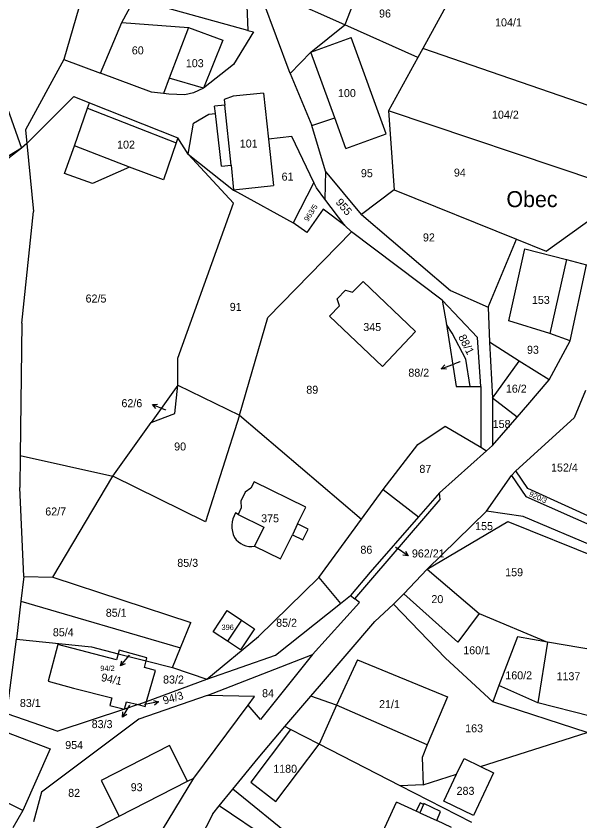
# Model space of a CAD drawing. Extents: x -593358 to -590116, y -1072518 to -1068420.
# Drawn here: x -591720.1 to -591600.3, y -1070728.7 to -1070557.8 of the extents above; entities that cross this region are included whole.
import ezdxf

# ---------------------------------------------------------------- set-up
doc = ezdxf.new("R2010")
doc.units = 0
for name, color, linetype in [('Názvosloví', 7, 'Continuous'), ('Parcela KN', 7, 'Continuous'), ('Parcelní číslo', 7, 'Continuous'), ('Parcelní číslo_stavební', 7, 'Continuous'), ('stavby - vnitřní kresba', 7, 'Continuous'), ('Vrstva 16', 7, 'Continuous')]:
    doc.layers.add(name, color=color, linetype=linetype)

msp = doc.modelspace()

# ---------------------------------------------------------------- linework, layer by layer
at = {"layer": 'Parcela KN'}
for p, q in [((-591700.37, -1070533.71), (-591709.96, -1070566.95)), ((-591671.59, -1070544.97), (-591670.83, -1070560.85)), ((-591647.2, -1070551.82), (-591650.26, -1070559.63)), ((-591697.64, -1070559.15), (-591694.95, -1070554.09)), ((-591670.83, -1070560.85), (-591694.95, -1070554.09)), ((-591661.85, -1070569.94), (-591667.67, -1070554.3)), ((-591628.45, -1070555.12), (-591633.68, -1070564.64)), ((-591702.13, -1070569.87), (-591697.64, -1070559.15)), ((-591697.64, -1070559.15), (-591683.44, -1070560.21)), ((-591683.44, -1070560.21), (-591687.54, -1070570.93)), ((-591683.44, -1070560.21), (-591676.15, -1070562.86)), ((-591657.46, -1070565.43), (-591650.26, -1070559.63)), ((-591634.74, -1070566.56), (-591650.26, -1070559.63)), ((-591676.15, -1070562.86), (-591680.28, -1070573.06)), ((-591657.46, -1070565.43), (-591648.91, -1070562.34)), ((-591641.5, -1070582.79), (-591648.91, -1070562.34)), ((-591725.94, -1070566.13), (-591718.97, -1070585.79)), ((-591657.46, -1070565.43), (-591661.85, -1070569.94)), ((-591633.68, -1070564.64), (-591634.74, -1070566.56)), ((-591591.64, -1070579.17), (-591633.68, -1070564.64)), ((-591709.96, -1070566.95), (-591718.13, -1070581.9)), ((-591709.96, -1070566.95), (-591702.13, -1070569.87)), ((-591634.74, -1070566.56), (-591641, -1070577.86)), ((-591691.32, -1070573.91), (-591702.13, -1070569.87)), ((-591687.54, -1070570.93), (-591688.81, -1070574.23)), ((-591680.28, -1070573.06), (-591687.54, -1070570.93)), ((-591661.85, -1070569.94), (-591657.25, -1070580.97)), ((-591707.85, -1070574.84), (-591717.83, -1070584.83)), ((-591707.85, -1070574.84), (-591704.51, -1070576.17)), ((-591688.81, -1070574.23), (-591691.32, -1070573.91)), ((-591673.96, -1070574.79), (-591675.88, -1070575.45)), ((-591667.5, -1070574.16), (-591673.96, -1070574.79)), ((-591667.5, -1070574.16), (-591666.46, -1070583.92)), ((-591704.9, -1070577.3), (-591704.51, -1070576.17)), ((-591704.51, -1070576.17), (-591685.71, -1070583.63)), ((-591675.88, -1070575.45), (-591675.78, -1070576.69)), ((-591707.71, -1070585.32), (-591704.9, -1070577.3)), ((-591675.78, -1070576.69), (-591677.94, -1070576.91)), ((-591677.76, -1070578.44), (-591677.94, -1070576.91)), ((-591595.29, -1070593.27), (-591641, -1070577.86)), ((-591641, -1070577.86), (-591639.75, -1070594.65)), ((-591682.43, -1070580.49), (-591679.13, -1070578.6)), ((-591679.13, -1070578.6), (-591677.76, -1070578.44)), ((-591676.46, -1070589.62), (-591677.76, -1070578.44)), ((-591657.25, -1070580.97), (-591652.39, -1070579.36)), ((-591650.02, -1070585.88), (-591652.39, -1070579.36)), ((-591683.56, -1070587.06), (-591682.43, -1070580.49)), ((-591654.33, -1070590.7), (-591657.25, -1070580.97)), ((-591718.13, -1070581.9), (-591717.83, -1070584.83)), ((-591661.52, -1070583.36), (-591666.46, -1070583.92)), ((-591656.8, -1070593.14), (-591661.52, -1070583.36)), ((-591650.02, -1070585.88), (-591641.5, -1070582.79)), ((-591717.83, -1070584.83), (-591718.97, -1070585.79)), ((-591717.83, -1070584.83), (-591716.37, -1070599.26)), ((-591686.08, -1070584.7), (-591688.76, -1070592.54)), ((-591685.71, -1070583.63), (-591686.08, -1070584.7)), ((-591683.56, -1070587.06), (-591685.71, -1070583.63)), ((-591666.46, -1070583.92), (-591665.41, -1070593.77)), ((-591718.97, -1070585.79), (-591725.69, -1070589.9)), ((-591718.97, -1070585.79), (-591723.12, -1070589.04)), ((-591709.78, -1070591.22), (-591707.71, -1070585.32)), ((-591683.56, -1070587.06), (-591673.9, -1070594.72)), ((-591673.91, -1070597.5), (-591683.56, -1070587.06)), ((-591695.98, -1070589.85), (-591703.88, -1070593.34)), ((-591688.76, -1070592.54), (-591695.98, -1070589.85)), ((-591676.46, -1070589.62), (-591674.43, -1070589.41)), ((-591674.43, -1070589.41), (-591673.89, -1070594.66)), ((-591703.88, -1070593.34), (-591709.78, -1070591.22)), ((-591654.33, -1070590.7), (-591654.47, -1070596.64)), ((-591646.73, -1070599.87), (-591654.33, -1070590.7)), ((-591656.8, -1070593.14), (-591661.24, -1070601.64)), ((-591656.25, -1070594.26), (-591656.8, -1070593.14)), ((-591673.9, -1070594.72), (-591673.08, -1070595.17)), ((-591673.89, -1070594.66), (-591665.41, -1070593.77)), ((-591673.08, -1070595.17), (-591661.24, -1070601.64)), ((-591654.47, -1070596.64), (-591656.25, -1070594.26)), ((-591639.75, -1070594.65), (-591646.73, -1070599.87)), ((-591639.75, -1070594.65), (-591613.79, -1070605.13)), ((-591650.26, -1070602.23), (-591654.47, -1070596.64)), ((-591685.73, -1070630.44), (-591673.91, -1070597.5)), ((-591654.82, -1070598.79), (-591658.3, -1070603.72)), ((-591650.26, -1070602.23), (-591654.82, -1070598.79)), ((-591718.9, -1070622.97), (-591716.37, -1070599.26)), ((-591646.73, -1070599.87), (-591627.76, -1070616.04)), ((-591607.46, -1070607.68), (-591596.91, -1070600.14)), ((-591658.3, -1070603.72), (-591661.24, -1070601.64)), ((-591666.62, -1070621.8), (-591648.81, -1070603.58)), ((-591648.81, -1070603.58), (-591650.26, -1070602.23)), ((-591629.57, -1070618.13), (-591648.81, -1070603.58)), ((-591619.78, -1070619.61), (-591613.79, -1070605.13)), ((-591613.79, -1070605.13), (-591607.46, -1070607.68)), ((-591615.37, -1070622.52), (-591612, -1070607.2)), ((-591612, -1070607.2), (-591603.17, -1070609.49)), ((-591603.17, -1070609.49), (-591598.88, -1070610.6)), ((-591602.35, -1070626.72), (-591598.88, -1070610.6)), ((-591648.64, -1070616.43), (-591646.38, -1070614.11)), ((-591646.38, -1070614.11), (-591635.21, -1070624.74)), ((-591651.9, -1070617.8), (-591650.13, -1070615.99)), ((-591650.13, -1070615.99), (-591648.64, -1070616.43)), ((-591627.76, -1070616.04), (-591619.78, -1070619.61)), ((-591653.52, -1070621.48), (-591651.35, -1070619.27)), ((-591651.35, -1070619.27), (-591651.9, -1070617.8)), ((-591622.07, -1070626.03), (-591629.57, -1070618.13)), ((-591629.57, -1070618.13), (-591628.62, -1070623.28)), ((-591619.78, -1070619.61), (-591619.54, -1070627)), ((-591672.63, -1070642.5), (-591666.62, -1070621.8)), ((-591642.25, -1070632.2), (-591653.52, -1070621.48)), ((-591606.67, -1070625.19), (-591615.37, -1070622.52)), ((-591718.9, -1070622.97), (-591719.22, -1070651.11)), ((-591627.47, -1070625.1), (-591628.62, -1070623.28)), ((-591628.62, -1070623.28), (-591626.58, -1070636.46)), ((-591635.21, -1070624.74), (-591642.25, -1070632.2)), ((-591624.53, -1070630.64), (-591627.47, -1070625.1)), ((-591621.38, -1070636.44), (-591622.07, -1070626.03)), ((-591602.35, -1070626.72), (-591606.67, -1070625.19)), ((-591619.54, -1070627), (-591618.89, -1070638.92)), ((-591613.18, -1070631.02), (-591619.54, -1070627)), ((-591606.82, -1070635.03), (-591602.35, -1070626.72)), ((-591685.71, -1070636.15), (-591685.73, -1070630.44)), ((-591623.64, -1070636.44), (-591624.53, -1070630.64)), ((-591606.82, -1070635.03), (-591613.18, -1070631.02)), ((-591685.71, -1070636.15), (-591691.4, -1070644.11)), ((-591686.38, -1070642.15), (-591685.71, -1070636.15)), ((-591685.71, -1070636.15), (-591672.63, -1070642.5)), ((-591611.36, -1070640.36), (-591606.82, -1070635.03)), ((-591626.58, -1070636.46), (-591623.64, -1070636.44)), ((-591623.64, -1070636.44), (-591621.38, -1070636.44)), ((-591621.38, -1070636.44), (-591621.36, -1070649.34)), ((-591599.11, -1070637.3), (-591601.55, -1070643.07)), ((-591618.89, -1070638.92), (-591618.85, -1070648.94)), ((-591613.61, -1070642.93), (-591618.89, -1070638.92)), ((-591613.61, -1070642.93), (-591611.36, -1070640.36)), ((-591691.4, -1070644.11), (-591686.38, -1070642.15)), ((-591672.63, -1070642.5), (-591679.82, -1070665.17)), ((-591672.63, -1070642.5), (-591646.69, -1070664.61)), ((-591618.85, -1070648.94), (-591613.61, -1070642.93)), ((-591613.94, -1070654.31), (-591601.55, -1070643.07)), ((-591699.54, -1070655.5), (-591691.4, -1070644.11)), ((-591634.72, -1070648.78), (-591628.96, -1070644.87)), ((-591628.96, -1070644.87), (-591621.36, -1070649.34)), ((-591642.12, -1070658.34), (-591634.72, -1070648.78)), ((-591630.16, -1070659), (-591620.12, -1070650.07)), ((-591621.36, -1070649.34), (-591620.12, -1070650.07)), ((-591620.12, -1070650.07), (-591618.85, -1070648.94)), ((-591719.22, -1070651.11), (-591719.3, -1070657.85)), ((-591719.22, -1070651.11), (-591699.54, -1070655.5)), ((-591614.83, -1070655.31), (-591613.94, -1070654.31)), ((-591611.35, -1070658.11), (-591613.94, -1070654.31)), ((-591712.31, -1070676.95), (-591699.54, -1070655.5)), ((-591679.82, -1070665.17), (-591699.54, -1070655.5)), ((-591669.51, -1070656.65), (-591670.21, -1070658.04)), ((-591658.56, -1070662.05), (-591669.51, -1070656.65)), ((-591620.12, -1070662.88), (-591614.83, -1070655.31)), ((-591614.83, -1070655.31), (-591611.82, -1070659.77)), ((-591718.42, -1070676.81), (-591719.3, -1070657.85)), ((-591670.21, -1070658.04), (-591671.46, -1070658.89)), ((-591646.69, -1070664.61), (-591642.12, -1070658.34)), ((-591642.12, -1070658.34), (-591634.59, -1070664.1)), ((-591586.6, -1070669.43), (-591611.35, -1070658.11)), ((-591671.46, -1070658.89), (-591672.38, -1070660.76)), ((-591630.16, -1070659), (-591634.59, -1070664.1)), ((-591629.96, -1070660.46), (-591630.16, -1070659)), ((-591611.82, -1070659.77), (-591552.93, -1070685.84)), ((-591672.38, -1070660.76), (-591672.27, -1070662.23)), ((-591644.28, -1070677.04), (-591629.96, -1070660.46)), ((-591672.92, -1070663.63), (-591673.48, -1070663.29)), ((-591672.27, -1070662.23), (-591672.92, -1070663.63)), ((-591660.3, -1070665.62), (-591658.56, -1070662.05)), ((-591620.12, -1070662.88), (-591632.76, -1070675.24)), ((-591612.33, -1070664.07), (-591620.12, -1070662.88)), ((-591655.75, -1070676.99), (-591646.69, -1070664.61)), ((-591634.59, -1070664.1), (-591644.84, -1070675.9)), ((-591632.76, -1070675.24), (-591615.64, -1070665.09)), ((-591615.64, -1070665.09), (-591594.73, -1070673.54)), ((-591554.36, -1070688.66), (-591612.33, -1070664.07)), ((-591658.06, -1070666.71), (-591660.3, -1070665.62)), ((-591659.2, -1070669.03), (-591658.06, -1070666.71)), ((-591663.94, -1070673.06), (-591661.4, -1070667.95)), ((-591661.4, -1070667.95), (-591659.2, -1070669.03)), ((-591669.41, -1070670.36), (-591663.94, -1070673.06)), ((-591637.73, -1070680.47), (-591632.76, -1070675.24)), ((-591632.76, -1070675.24), (-591621.7, -1070684.64)), ((-591718.42, -1070676.81), (-591719.06, -1070682.05)), ((-591718.42, -1070676.81), (-591712.31, -1070676.95)), ((-591712.31, -1070676.95), (-591683, -1070686.57)), ((-591668.59, -1070689.56), (-591655.75, -1070676.99)), ((-591655.75, -1070676.99), (-591651.16, -1070682.49)), ((-591644.84, -1070675.9), (-591649.02, -1070680.82)), ((-591648.1, -1070681.55), (-591644.28, -1070677.04)), ((-591651.16, -1070682.49), (-591649.02, -1070680.82)), ((-591649.02, -1070680.82), (-591648.1, -1070681.55)), ((-591639.92, -1070682.65), (-591637.73, -1070680.47)), ((-591626.23, -1070690.72), (-591637.73, -1070680.47)), ((-591719.06, -1070682.05), (-591720.03, -1070690.07)), ((-591719.06, -1070682.05), (-591685.16, -1070691.91)), ((-591665.01, -1070693.49), (-591651.16, -1070682.49)), ((-591657.09, -1070693.37), (-591647.16, -1070682.29)), ((-591647.16, -1070682.29), (-591648.1, -1070681.55)), ((-591678.21, -1070688.52), (-591675.25, -1070684.04)), ((-591675.25, -1070684.04), (-591672.19, -1070686.07)), ((-591643.86, -1070686.32), (-591639.92, -1070682.65)), ((-591628.88, -1070694.16), (-591639.92, -1070682.65)), ((-591621.7, -1070684.64), (-591626.23, -1070690.72)), ((-591621.7, -1070684.64), (-591607.21, -1070690.7)), ((-591685.16, -1070691.91), (-591683, -1070686.57)), ((-591672.19, -1070686.07), (-591669.44, -1070687.93)), ((-591655.66, -1070700.07), (-591643.86, -1070686.32)), ((-591675.21, -1070690.55), (-591678.21, -1070688.52)), ((-591669.44, -1070687.93), (-591672.4, -1070692.39)), ((-591722.1, -1070705.85), (-591720.03, -1070690.07)), ((-591720.03, -1070690.07), (-591704.11, -1070691.76)), ((-591679.6, -1070698.59), (-591668.59, -1070689.56)), ((-591672.4, -1070692.39), (-591675.21, -1070690.55)), ((-591613.59, -1070689.6), (-591617.51, -1070699.97)), ((-591607.21, -1070690.7), (-591613.59, -1070689.6)), ((-591607.21, -1070690.7), (-591609.27, -1070703.65)), ((-591596.78, -1070692.48), (-591607.21, -1070690.7)), ((-591711.23, -1070691.22), (-591713.27, -1070699)), ((-591698.77, -1070694.49), (-591711.23, -1070691.22)), ((-591704.11, -1070691.76), (-591698.43, -1070693.2)), ((-591698.23, -1070692.43), (-591698.43, -1070693.2)), ((-591692.29, -1070694.04), (-591698.23, -1070692.43)), ((-591686.87, -1070696.13), (-591685.16, -1070691.91)), ((-591698.43, -1070693.2), (-591698.77, -1070694.49)), ((-591698.43, -1070693.2), (-591692.46, -1070694.71)), ((-591692.46, -1070694.71), (-591692.29, -1070694.04)), ((-591679.6, -1070698.59), (-591665.01, -1070693.49)), ((-591679.5, -1070702.09), (-591657.09, -1070693.37)), ((-591657.09, -1070693.37), (-591668.16, -1070707.19)), ((-591647.54, -1070694.48), (-591652.04, -1070704.14)), ((-591647.54, -1070694.48), (-591628.43, -1070702.35)), ((-591618.82, -1070703.42), (-591628.88, -1070694.16)), ((-591692.83, -1070696.13), (-591692.46, -1070694.71)), ((-591690.47, -1070696.73), (-591692.83, -1070696.13)), ((-591692.46, -1070694.71), (-591686.87, -1070696.13)), ((-591686.87, -1070696.13), (-591679.6, -1070698.59)), ((-591692.39, -1070703.32), (-591690.47, -1070696.73)), ((-591713.27, -1070699), (-591707.88, -1070700.52)), ((-591692.39, -1070703.32), (-591679.6, -1070698.59)), ((-591707.88, -1070700.52), (-591699.76, -1070702.59)), ((-591657.47, -1070702.19), (-591655.66, -1070700.07)), ((-591617.51, -1070699.97), (-591618.82, -1070703.42)), ((-591609.27, -1070703.65), (-591617.51, -1070699.97)), ((-591699.76, -1070702.59), (-591700.15, -1070704.21)), ((-591679.5, -1070702.09), (-591694.04, -1070707.08)), ((-591669.45, -1070702.28), (-591679.5, -1070702.09)), ((-591670.8, -1070704.09), (-591669.45, -1070702.28)), ((-591662.99, -1070708.68), (-591657.47, -1070702.19)), ((-591652.04, -1070704.14), (-591657.47, -1070702.19)), ((-591628.43, -1070702.35), (-591632.75, -1070712.56)), ((-591700.15, -1070704.21), (-591697.09, -1070704.94)), ((-591697.09, -1070704.94), (-591696.66, -1070703.38)), ((-591694.18, -1070703.98), (-591697.09, -1070704.94)), ((-591696.66, -1070703.38), (-591694.18, -1070703.98)), ((-591694.18, -1070703.98), (-591692.39, -1070703.32)), ((-591694.18, -1070703.98), (-591692.7, -1070704.39)), ((-591692.7, -1070704.39), (-591692.39, -1070703.32)), ((-591682.35, -1070719.59), (-591670.8, -1070704.09)), ((-591668.16, -1070707.19), (-591670.8, -1070704.09)), ((-591598.77, -1070709.94), (-591618.82, -1070703.42)), ((-591598.13, -1070706.43), (-591609.27, -1070703.65)), ((-591722.1, -1070705.85), (-591711.25, -1070709.63)), ((-591697.09, -1070704.94), (-591711.25, -1070709.63)), ((-591694.04, -1070707.08), (-591714.68, -1070722.61)), ((-591723.89, -1070709.2), (-591712.87, -1070713.39)), ((-591661.82, -1070709.28), (-591670.25, -1070720.49)), ((-591668.68, -1070715.35), (-591662.99, -1070708.68)), ((-591661.82, -1070709.28), (-591662.99, -1070708.68)), ((-591655.71, -1070712.41), (-591661.82, -1070709.28)), ((-591621.42, -1070717.16), (-591598.77, -1070709.94)), ((-591687.51, -1070712.7), (-591702.05, -1070720.1)), ((-591683.68, -1070720.27), (-591687.51, -1070712.7)), ((-591664.88, -1070724.55), (-591655.71, -1070712.41)), ((-591638.49, -1070721.22), (-591655.71, -1070712.41)), ((-591632.75, -1070712.56), (-591633.79, -1070715.26)), ((-591712.87, -1070713.39), (-591718.7, -1070726.48)), ((-591674.03, -1070721.94), (-591668.68, -1070715.35)), ((-591633.79, -1070715.26), (-591633.6, -1070721.05)), ((-591626.51, -1070718.79), (-591624.92, -1070715.45)), ((-591624.92, -1070715.45), (-591621.42, -1070717.16)), ((-591621.42, -1070717.16), (-591618.64, -1070718.52)), ((-591702.05, -1070720.1), (-591698.2, -1070727.71)), ((-591688.96, -1070730.57), (-591682.35, -1070719.59)), ((-591683.68, -1070720.27), (-591682.35, -1070719.59)), ((-591633.6, -1070721.05), (-591626.51, -1070718.79)), ((-591629.23, -1070724.47), (-591626.51, -1070718.79)), ((-591618.64, -1070718.52), (-591622.94, -1070727.54)), ((-591718.7, -1070726.48), (-591730.3, -1070720.71)), ((-591698.2, -1070727.71), (-591683.68, -1070720.27)), ((-591670.25, -1070720.49), (-591664.88, -1070724.55)), ((-591633.6, -1070721.05), (-591638.49, -1070721.22)), ((-591623.26, -1070729.02), (-591638.49, -1070721.22)), ((-591714.68, -1070722.61), (-591716.43, -1070728.87)), ((-591676.93, -1070725.51), (-591674.03, -1070721.94)), ((-591634.98, -1070753.71), (-591674.03, -1070721.94)), ((-591643.97, -1070734.91), (-591639.24, -1070724.7)), ((-591635.08, -1070726.63), (-591639.24, -1070724.7)), ((-591634.25, -1070724.83), (-591635.08, -1070726.63)), ((-591633.5, -1070725.18), (-591634.25, -1070724.83)), ((-591633.44, -1070725.03), (-591633.5, -1070725.18)), ((-591629.89, -1070726.71), (-591633.44, -1070725.03)), ((-591622.94, -1070727.54), (-591629.23, -1070724.47)), ((-591718.7, -1070726.48), (-591720.77, -1070730.15)), ((-591678.3, -1070727.2), (-591676.93, -1070725.51)), ((-591634.98, -1070753.71), (-591676.93, -1070725.51)), ((-591630.73, -1070728.64), (-591629.89, -1070726.71)), ((-591712.74, -1070735.17), (-591698.2, -1070727.71)), ((-591678.3, -1070727.2), (-591683.56, -1070737.32)), ((-591627.59, -1070730.09), (-591630.73, -1070728.64))]:
    msp.add_line(p, q, dxfattribs=at)
for centre, radius, start, end in [((-591668.823, -1070666.068), 5.423, 149.17999, 206.40633), ((-591670.145, -1070666.24), 4.185, 212.36302, 280.11101)]:
    msp.add_arc(centre, radius, start, end, dxfattribs=at)
at = {"layer": 'stavby - vnitřní kresba'}
for p, q in [((-591650.26, -1070559.63), (-591665.33, -1070552.91)), ((-591669.67, -1070561.08), (-591673.87, -1070568.08)), ((-591670.83, -1070560.85), (-591669.67, -1070561.08)), ((-591652.39, -1070579.36), (-591657.46, -1070565.43)), ((-591673.87, -1070568.08), (-591680.28, -1070573.06)), ((-591680.28, -1070573.06), (-591682.42, -1070574.06)), ((-591687.62, -1070574.38), (-591688.81, -1070574.23)), ((-591684.28, -1070574.46), (-591687.62, -1070574.38)), ((-591682.42, -1070574.06), (-591684.28, -1070574.46)), ((-591704.9, -1070577.3), (-591686.08, -1070584.7)), ((-591674.43, -1070589.41), (-591675.78, -1070576.69)), ((-591695.98, -1070589.85), (-591707.71, -1070585.32)), ((-591603.17, -1070609.49), (-591606.67, -1070625.19)), ((-591618.89, -1070638.92), (-591613.18, -1070631.02)), ((-591672.92, -1070663.63), (-591667.46, -1070666.32)), ((-591667.46, -1070666.32), (-591669.41, -1070670.36)), ((-591660.3, -1070665.62), (-591661.4, -1070667.95)), ((-591672.19, -1070686.07), (-591675.21, -1070690.55)), ((-591652.04, -1070704.14), (-591655.71, -1070712.41)), ((-591632.75, -1070712.56), (-591652.04, -1070704.14)), ((-591633.5, -1070725.18), (-591634.33, -1070726.97)), ((-591634.33, -1070726.97), (-591635.08, -1070726.63)), ((-591634.33, -1070726.97), (-591630.73, -1070728.64))]:
    msp.add_line(p, q, dxfattribs=at)
at = {"layer": 'Vrstva 16'}
for p, q in [((-591625.79, -1070631.19), (-591626.95, -1070631.62)), ((-591629.767, -1070632.652), (-591626.95, -1070631.62)), ((-591691.145, -1070640.255), (-591688.36, -1070641.37)), ((-591639.5, -1070670.55), (-591639.28, -1070670.7)), ((-591636.813, -1070672.407), (-591639.28, -1070670.7)), ((-591697.94, -1070695.762), (-591695.97, -1070693.5)), ((-591697.515, -1070706.647), (-591695.93, -1070704.1)), ((-591689.837, -1070703.4), (-591692.78, -1070703.98))]:
    msp.add_line(p, q, dxfattribs=at)
for points in [[(-591628.656, -1070632.778), (-591629.767, -1070632.652), (-591629, -1070631.839)], [(-591690.403, -1070641.091), (-591691.145, -1070640.255), (-591690.031, -1070640.162)], [(-591637.351, -1070671.427), (-591636.813, -1070672.407), (-591637.92, -1070672.249)], [(-591696.907, -1070695.337), (-591697.94, -1070695.762), (-591697.661, -1070694.68)], [(-591690.914, -1070703.103), (-591689.837, -1070703.4), (-591690.721, -1070704.084)], [(-591696.562, -1070706.062), (-591697.515, -1070706.647), (-591697.411, -1070705.534)]]:
    msp.add_lwpolyline(points, dxfattribs=at)

# ---------------------------------------------------------------- texts
at = {"layer": 'Názvosloví'}
msp.add_text('Obec', height=3.4, dxfattribs=at).set_placement((-591615.914, -1070598.34))
at = {"layer": 'Parcelní číslo'}
for s, height, p in [('96', 1.7, (-591642.975, -1070558.06)), ('104/1', 1.7, (-591618.324, -1070559.95)), ('60', 1.7, (-591695.512, -1070565.89)), ('104/2', 1.7, (-591618.976, -1070579.55)), ('95', 1.7, (-591646.832, -1070591.98)), ('94', 1.7, (-591627.075, -1070591.85)), ('61', 1.7, (-591663.687, -1070592.71)), ('92', 1.7, (-591633.649, -1070605.62)), ('62/5', 1.7, (-591705.334, -1070618.6)), ('91', 1.7, (-591674.697, -1070620.38)), ('93', 1.7, (-591611.542, -1070629.48)), ('89', 1.7, (-591658.432, -1070637.97)), ('62/6', 0.1, (-591688.339, -1070641.37)), ('158', 1.7, (-591618.823, -1070645.24)), ('90', 1.7, (-591686.512, -1070650.02)), ('87', 1.7, (-591634.411, -1070654.78)), ('152/4', 1.7, (-591606.426, -1070654.49)), ('62/7', 1.7, (-591713.897, -1070663.83)), ('155', 1.7, (-591622.56, -1070666.94)), ('86', 1.7, (-591646.932, -1070671.95)), ('962/21', 0.1, (-591639.731, -1070670.55)), ('85/3', 1.7, (-591685.845, -1070674.74)), ('159', 1.7, (-591616.173, -1070676.73)), ('85/1', 1.7, (-591701.039, -1070685.34)), ('85/2', 1.7, (-591664.841, -1070687.47)), ('85/4', 1.7, (-591712.287, -1070689.48)), ('160/1', 1.7, (-591625.084, -1070693.31)), ('83/2', 1.7, (-591688.871, -1070699.52)), ('160/2', 1.7, (-591616.146, -1070698.63)), ('1137', 1.7, (-591605.264, -1070698.82)), ('84', 1.7, (-591667.832, -1070702.42)), ('83/1', 1.7, (-591719.29, -1070704.5)), ('83/3', 0.1, (-591695.916, -1070704.1)), ('163', 1.7, (-591624.673, -1070709.88)), ('954', 1.7, (-591709.661, -1070713.43)), ('1180', 1.7, (-591665.461, -1070718.47)), ('82', 1.7, (-591709.035, -1070723.59))]:
    msp.add_text(s, height=height, dxfattribs=at).set_placement(p)
for s, height, rotation, p in [('955', 1.7, 310.14206, (-591652.3, -1070597.374)), ('963/5', 1.14, 57.63956, (-591658.06, -1070601.511)), ('88/1', 1.7, 296.67755, (-591626.19, -1070625.891)), ('88/2', 0.1, 281.37957, (-591625.823, -1070631.004)), ('920/3', 1.14, 335.75327, (-591611.214, -1070659.673))]:
    msp.add_text(s, height=height, rotation=rotation, dxfattribs=at).set_placement(p)
at = {"layer": 'Parcelní číslo_stavební'}
for s, height, p in [('103', 1.7, (-591684.03, -1070568.62)), ('100', 1.7, (-591651.7, -1070574.97)), ('102', 1.7, (-591698.637, -1070585.92)), ('101', 1.7, (-591672.565, -1070585.68)), ('153', 1.7, (-591610.5, -1070618.9)), ('345', 1.7, (-591646.328, -1070624.66)), ('16/2', 1.7, (-591616.029, -1070637.75)), ('375', 1.7, (-591668.028, -1070665.28)), ('20', 1.7, (-591631.855, -1070682.44)), ('396', 1.14, (-591676.459, -1070688.15)), ('94/2', 0.1, (-591695.956, -1070693.5)), ('21/1', 1.7, (-591642.971, -1070704.74)), ('94/3', 0.1, (-591692.766, -1070703.98)), ('93', 1.7, (-591695.742, -1070722.39)), ('283', 1.7, (-591626.502, -1070723.16))]:
    msp.add_text(s, height=height, dxfattribs=at).set_placement(p)
msp.add_text('94/1', height=1.7, rotation=348.01456, dxfattribs=at).set_placement((-591702.144, -1070698.962))
at = {"layer": 'Vrstva 16'}
for s, height, p in [('88/2', 1.7, (-591636.75, -1070634.35)), ('62/6', 1.7, (-591697.713, -1070640.83)), ('962/21', 1.7, (-591635.993, -1070672.74)), ('94/2', 1.14, (-591702.208, -1070696.87)), ('83/3', 1.7, (-591704.037, -1070708.99))]:
    msp.add_text(s, height=height, dxfattribs=at).set_placement(p)
msp.add_text('94/3', height=1.7, rotation=16.50118, dxfattribs=at).set_placement((-591688.631, -1070704.008))

doc.saveas('drawing.dxf')
